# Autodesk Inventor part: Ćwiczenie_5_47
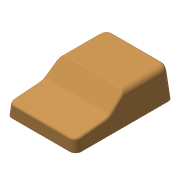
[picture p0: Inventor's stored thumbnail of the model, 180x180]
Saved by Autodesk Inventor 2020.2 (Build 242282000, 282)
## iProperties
Created: 2005-04
Part Number: Ćwiczenie_5_47
Document SubType Name: Modeling
Designer: F.Stasiak
Manufacturer: Standard
Standards Organization: Custom
Density: 1 g/cm^3
Material: Ogólny
Appearance: Pomarańczowy (blady)
Manager: www.cadconsulting.pl
Company: Fabian Stasiak CAD Consulting
Author: F.Stasiak
Subject: Zbiór ćwiczeń. Autodesk Inventor 2020. Kurs podstawowy
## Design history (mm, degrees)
sketch "Szkic2"
  geometry: L1 (-42.5, 10)-(-42.5, 0); L2 (-42.5, 0)-(42.5, 0); L3 (42.5, 0)-(42.5, 25); L4 (42.5, 25)-(2.5, 25); L5 (2.5, 25)-(-12.614, 12.615); L6 (-12.614, 12.615)-(-42.5, 10); 2 further points
  constraints: 12 end point, 2 parallel, 1 coincident, 1 midpoint, 1 perpendicular, 1 vertical
  dimensions: "d0" = 85 distance of L1.end L2.end; "d1" = 25 distance of L2.end L3.end; "d2" = 10 distance of L1.start L1.end; "d3" = 40 distance of L3.end L4.end; "d4" = 30 distance of L5.end L1.start; "d85" = 95 deg angle of L6 L1
extrude "Wyciągnięcie proste1" new body sketch "Szkic2" stored distance "d5" = 60; taper "d6" = 0 deg
feature "Szkic powierzchni1" dims angle "d22" = 5 deg
node "Bryła1"
node "Korpusy bryłowe"
node "Korpusy powierzchniowe"
fillet "Zaokrąglenie1" dims "d86" = 5, "d87" = 2, "d88" = 10
